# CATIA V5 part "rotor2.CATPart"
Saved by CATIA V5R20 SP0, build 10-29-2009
Part number: rotor2
Bounding box of the stored display mesh (mm): x -15 to 15, y -15 to 35, z -10 to 10
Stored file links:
  D:\Documents and Settings\mosavian\My Documents\DMU Project3\New Folder\rotor2.CATPart
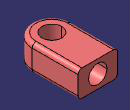
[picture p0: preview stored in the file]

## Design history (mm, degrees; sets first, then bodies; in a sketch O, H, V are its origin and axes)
Body1 (main body)
  Sketch1 on xy-plane, origin (0, 0, 0), H (1, 0, 0), V (0, 1, 0)
    circle A1 centre (0, 0) radius 7.5
    construction line L1 (0, 0) -> (0, 35)
    point P1 (0, 35)
    line L2 (-15, 0) -> (-15, 35)
    line L3 (15, 35) -> (15, 0)
    arc A2 centre (0, 0) radius 15 from (15, 0) to (-15, 0) cw
    line L4 (-15, 35) -> (15, 35)
    radius A1 = 7.5
    radius A2 = 15
    length L1 = 35
    vertical: L1 V, L3 V, L2 V
    tangency: A2 L2, A2 L3
    horizontal: L4 H
    coincidence: L4 P1
  Pad1: profile Sketch1, direction (0, 0, 1), length 10, mirrored extent
  Fillet1: radius 3, on edge [face of Pad1 from Sketch1.L3 | end face of Pad1]; edge [start face of Pad1 | face of Pad1 from Sketch1.L3]
  Sketch2 on face of Pad1 from Sketch1.L4, origin (0, 35, 0), H (-1, 0, 0), V (0, 0, 1)
    circle A1 centre (0, 0) radius 7
    radius A1 = 7
  Pocket1: profile Sketch2, direction (0, -1, 0), length 15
